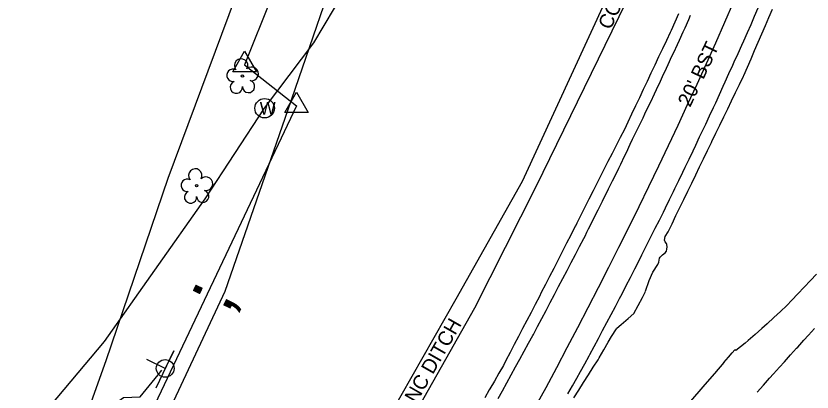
# Model space of a CAD drawing. Extents: x 1806071 to 1809844, y 912722 to 917035.
# Drawn here: x 1807362.2 to 1807582.5, y 914421.2 to 914525.2 of the extents above; entities that cross this region are included whole.
import ezdxf

# ---------------------------------------------------------------- set-up
doc = ezdxf.new("R2010")
doc.units = 0
for name, color, linetype in [('Exist Horizontal Alignment', 7, 'Continuous'), ('Exist Other Culture Fence Line', 7, 'Continuous'), ('Exist Right of Way Control of Access CA Symbol CELL', 7, 'Continuous'), ('Exist Right of Way Line', 7, 'Continuous'), ('Exist Right of Way Monument CELL', 7, 'Continuous'), ('Exist Roads Curbs', 7, 'Continuous'), ('Exist Roads EOP', 7, 'Continuous'), ('Exist Roads EOP Other', 7, 'Continuous'), ('Exist Roads EOP Text', 7, 'Continuous'), ('Exist Roads EOT', 7, 'Continuous'), ('Exist Structure Minor Paved Ditch or Gutter', 7, 'Continuous'), ('Exist Structure Minor Paved Ditch or Gutter Text', 7, 'Continuous'), ('Exist Utilities Power Joint Use Telephone CELL', 7, 'Continuous'), ('Exist Utilities Telephone UG Cable SUE LOS B', 7, 'Continuous'), ('Exist Utilities Water Manhole CELL', 7, 'Continuous'), ('Exist Utilities Water UG Line SUE LOS B', 7, 'Continuous'), ('Exist Vegetation Tree CELL', 7, 'Continuous')]:
    doc.layers.add(name, color=color, linetype=linetype)

msp = doc.modelspace()

# ---------------------------------------------------------------- linework, layer by layer
at = {"layer": 'Exist Horizontal Alignment'}
msp.add_arc((1806248.23, 915102.55), 1432.39, 321.65643, 337.65643, dxfattribs=at)
at = {"layer": 'Exist Other Culture Fence Line'}
for points in [[(1807420.06, 914449.08), (1807437.56, 914499.34), (1807454.43, 914548.48), (1807469.99, 914594.83), (1807485.68, 914641.45), (1807500.22, 914684.48), (1807514.26, 914726.68), (1807527.29, 914765.96), (1807541.47, 914807.7), (1807554.84, 914848.72), (1807568.79, 914890.48), (1807589.07, 914952.46), (1807599.72, 914988.41), (1807613.51, 915037.41), (1807624.28, 915075.41), (1807640.3, 915130.15), (1807650.98, 915169.04)], [(1806951.65, 913841.13), (1806983.44, 913875.99), (1807013.14, 913908.4), (1807047.06, 913945.66), (1807072.1, 913972.65), (1807103.97, 914007.22), (1807136.36, 914042.6), (1807170.27, 914079.29), (1807203.63, 914115.49), (1807234.9, 914151.15), (1807263.39, 914186.29), (1807290.32, 914222.94), (1807319.14, 914263.94), (1807345.33, 914304.29), (1807362.24, 914332.3), (1807387.67, 914379.81), (1807420.06, 914449.08)]]:
    msp.add_lwpolyline(points, dxfattribs=at)
at = {"layer": 'Exist Right of Way Control of Access CA Symbol CELL'}
msp.add_line((1807417.18, 914452.58), (1807417.18, 914452.58), dxfattribs=at)
at = {"layer": 'Exist Right of Way Line'}
for p, q in [((1807526.22, 914764.33), (1807425.5, 914511.68)), ((1807425.5, 914511.68), (1807439.85, 914500.36)), ((1807439.85, 914500.36), (1807384.85, 914384.43))]:
    msp.add_line(p, q, dxfattribs=at)
at = {"layer": 'Exist Right of Way Monument CELL'}
for p, q in [((1807425.5, 914511.68), (1807425.5, 914511.68)), ((1807439.85, 914500.36), (1807439.85, 914500.36))]:
    msp.add_line(p, q, dxfattribs=at)
for points in [[(1807422.25, 914509.79), (1807425.5, 914515.43), (1807428.74, 914509.79)], [(1807436.6, 914498.47), (1807439.85, 914504.11), (1807443.1, 914498.47)]]:
    msp.add_lwpolyline(points, close=True, dxfattribs=at)
at = {"layer": 'Exist Roads Curbs'}
for points in [[(1807558.07, 914429.35), (1807559.37, 914430.87), (1807560.35, 914432.01), (1807561.12, 914432.9)], [(1807558.06, 914429.35), (1807555.47, 914426.31), (1807552.85, 914423.3), (1807548.27, 914418)]]:
    msp.add_lwpolyline(points, dxfattribs=at)
at = {"layer": 'Exist Roads EOP'}
msp.add_line((1807364.11, 914365.32), (1807387.16, 914429.97), dxfattribs=at)
for points in [[(1807545.5, 914525.78), (1807544.48, 914523.49), (1807543.47, 914521.21), (1807543.23, 914520.67), (1807542.16, 914518.41), (1807541.09, 914516.14), (1807540.02, 914513.88), (1807538.96, 914511.62), (1807537.89, 914509.36), (1807536.82, 914507.1), (1807535.75, 914504.84), (1807534.69, 914502.58), (1807533.62, 914500.32), (1807532.55, 914498.06), (1807531.48, 914495.8), (1807530.55, 914493.83), (1807529.41, 914491.61), (1807528.27, 914489.38), (1807527.13, 914487.16), (1807526, 914484.93), (1807524.86, 914482.71), (1807524.13, 914481.29), (1807523.01, 914479.06), (1807521.88, 914476.82), (1807520.76, 914474.59), (1807519.64, 914472.36), (1807518.51, 914470.12), (1807517.39, 914467.89), (1807516.99, 914467.09)], [(1807536.4, 914449.07), (1807537.42, 914452.07), (1807538.47, 914454.36), (1807539.78, 914456.49), (1807540.05, 914457.08), (1807540.27, 914458.24), (1807540.48, 914458.54), (1807541.12, 914459.17), (1807541.85, 914459.66), (1807542.16, 914460.15), (1807542.3, 914460.71), (1807542.39, 914461.39), (1807542.34, 914461.98), (1807542.18, 914462.32), (1807541.82, 914462.76), (1807541.68, 914463.25), (1807541.82, 914464.18), (1807542.65, 914465.49), (1807543.74, 914467.74), (1807544.83, 914469.99), (1807545.92, 914472.24), (1807547.01, 914474.48), (1807548.1, 914476.73), (1807549.19, 914478.98), (1807550.28, 914481.23), (1807551.37, 914483.48), (1807552.46, 914485.73), (1807553.55, 914487.98), (1807554.64, 914490.23), (1807554.79, 914490.53), (1807555.88, 914492.78), (1807556.96, 914495.03), (1807558.05, 914497.28), (1807559.14, 914499.53), (1807560.23, 914501.78), (1807561.31, 914504.03), (1807562.4, 914506.28), (1807563.49, 914508.53), (1807563.6, 914508.77), (1807564.6, 914511.06), (1807565.59, 914513.36), (1807566.59, 914515.65), (1807567.59, 914517.94), (1807568.58, 914520.24), (1807569.58, 914522.53), (1807570.56, 914524.83), (1807571.55, 914527.12)], [(1807516.98, 914467.07), (1807515.72, 914464.59), (1807514.58, 914462.36), (1807513.44, 914460.14), (1807513.27, 914459.81), (1807512.13, 914457.58), (1807510.99, 914455.36), (1807509.85, 914453.13), (1807508.7, 914450.91), (1807507.56, 914448.69), (1807507.03, 914447.65), (1807505.87, 914445.44), (1807504.72, 914443.22), (1807503.56, 914441), (1807502.4, 914438.79), (1807501.25, 914436.57), (1807500.09, 914434.35), (1807498.94, 914432.14), (1807497.78, 914429.92), (1807497.07, 914428.55), (1807495.82, 914426.38), (1807494.58, 914424.22), (1807493.33, 914422.05), (1807493.19, 914421.8), (1807491.94, 914419.64)], [(1807583.75, 914453.83), (1807582.03, 914452.02), (1807580.31, 914450.2), (1807578.58, 914448.39), (1807576.86, 914446.58), (1807575.54, 914445.18), (1807573.71, 914443.49), (1807571.87, 914441.79), (1807570.04, 914440.09), (1807568.62, 914438.78), (1807566.73, 914437.14), (1807564.84, 914435.5), (1807563.97, 914434.75), (1807561.37, 914432.69), (1807561.12, 914432.9)], [(1807516.57, 914419.61), (1807517.91, 914421.71), (1807519.26, 914423.82), (1807520.6, 914425.93), (1807521.94, 914428.04), (1807523.29, 914430.15), (1807523.62, 914430.66), (1807524.84, 914432.85), (1807526.06, 914435.03), (1807526.95, 914436.61), (1807528.33, 914438.7), (1807528.42, 914438.85), (1807529.69, 914439.86), (1807531.56, 914441.52), (1807533.18, 914442.96), (1807534.35, 914445.17), (1807535.52, 914447.38), (1807536.39, 914449.03)]]:
    msp.add_lwpolyline(points, dxfattribs=at)
at = {"layer": 'Exist Roads EOP Other'}
for p, q in [((1807404.33, 914480.31), (1807453.9, 914613.77)), ((1807387.16, 914429.97), (1807404.33, 914480.31))]:
    msp.add_line(p, q, dxfattribs=at)
at = {"layer": 'Exist Roads EOT'}
for points in [[(1807532.23, 914452.9), (1807533.44, 914455.26), (1807534.25, 914456.89), (1807535.37, 914459.12), (1807536.5, 914461.35), (1807536.67, 914461.7), (1807537.8, 914463.94), (1807538.92, 914466.17), (1807539.09, 914466.51), (1807540.23, 914468.74), (1807541.36, 914470.97), (1807541.97, 914472.17), (1807543.06, 914474.42), (1807544.15, 914476.67), (1807544.54, 914477.47), (1807545.63, 914479.72), (1807546.72, 914481.98), (1807547.4, 914483.4), (1807548.48, 914485.65), (1807549.56, 914487.91), (1807550.32, 914489.49), (1807551.37, 914491.75), (1807552.43, 914494.02), (1807553.05, 914495.33), (1807554.12, 914497.59), (1807555.19, 914499.85), (1807555.83, 914501.2), (1807556.85, 914503.48), (1807557.88, 914505.76), (1807558.45, 914507.02), (1807559.49, 914509.3), (1807560.53, 914511.57), (1807560.97, 914512.53), (1807561.99, 914514.82), (1807563.01, 914517.1), (1807563.56, 914518.33), (1807564.59, 914520.61), (1807565.6, 914522.86), (1807566.59, 914525.16), (1807567.6, 914527.49)], [(1807519.67, 914464.35), (1807520.19, 914465.39), (1807520.66, 914466.34), (1807521.42, 914467.9), (1807522.14, 914469.31), (1807523.26, 914471.55), (1807523.38, 914471.78), (1807524.5, 914474.02), (1807524.82, 914474.68), (1807525.95, 914476.91), (1807526.2, 914477.41), (1807527.31, 914479.65), (1807527.9, 914480.82), (1807528.99, 914483.08), (1807529.54, 914484.23), (1807530.63, 914486.48), (1807531.11, 914487.46), (1807532.18, 914489.72), (1807532.84, 914491.1), (1807533.93, 914493.35), (1807534.64, 914494.81), (1807535.73, 914497.06), (1807536.25, 914498.15), (1807537.33, 914500.41), (1807537.83, 914501.46), (1807538.9, 914503.72), (1807539.46, 914504.91), (1807540.52, 914507.17), (1807541.12, 914508.46), (1807542.18, 914510.73), (1807542.68, 914511.78), (1807543.72, 914514.05), (1807544.2, 914515.09), (1807545.25, 914517.36), (1807545.8, 914518.55), (1807546.82, 914520.84), (1807547.33, 914521.97), (1807548.35, 914524.25), (1807548.88, 914525.43)], [(1807495.6, 914419.38), (1807496.81, 914421.57), (1807498.01, 914423.75), (1807499.22, 914425.94), (1807500.43, 914428.13), (1807501.64, 914430.32), (1807502.85, 914432.51), (1807504.06, 914434.7), (1807505.27, 914436.88), (1807505.39, 914437.11), (1807506.55, 914439.32), (1807507.71, 914441.54), (1807508.87, 914443.75), (1807510.04, 914445.97), (1807511.2, 914448.18), (1807512.36, 914450.39), (1807513.52, 914452.61), (1807514.68, 914454.82), (1807515.84, 914457.04), (1807517, 914459.25), (1807518.16, 914461.47), (1807519.32, 914463.68), (1807519.66, 914464.32)], [(1807514.91, 914420.74), (1807516.17, 914422.9), (1807517.42, 914425.07), (1807518.39, 914426.84), (1807519.59, 914429.03), (1807520.8, 914431.23), (1807521, 914431.6), (1807522.17, 914433.81), (1807523.35, 914436.01), (1807524.53, 914438.22), (1807525.71, 914440.42), (1807526.88, 914442.63), (1807528.06, 914444.84), (1807529.24, 914447.04), (1807529.94, 914448.41), (1807531.08, 914450.64), (1807532.21, 914452.87)], [(1807567.26, 914421.2), (1807569, 914423.15), (1807570.69, 914425), (1807571.8, 914426.22), (1807573.48, 914428.07), (1807574.86, 914429.6), (1807576.53, 914431.46), (1807578.21, 914433.31), (1807578.53, 914433.66), (1807580.21, 914435.51), (1807581.5, 914436.94), (1807583.18, 914438.78)]]:
    msp.add_lwpolyline(points, dxfattribs=at)
at = {"layer": 'Exist Structure Minor Paved Ditch or Gutter'}
for points in [[(1807546.15, 914577.54), (1807529.9, 914539.49), (1807502.29, 914479.4), (1807483.96, 914446.87), (1807459.55, 914404.11), (1807434.92, 914363.15), (1807436.63, 914361.7)], [(1807439.65, 914359.8), (1807464.74, 914401.26), (1807489.22, 914444.52), (1807506.17, 914478.05), (1807534.83, 914536.85), (1807551.23, 914575.61)]]:
    msp.add_lwpolyline(points, dxfattribs=at)
at = {"layer": 'Exist Utilities Power Joint Use Telephone CELL'}
msp.add_line((1807403.51, 914427.75), (1807403.51, 914427.75), dxfattribs=at)
msp.add_lwpolyline([(1807400.97, 914422.38), (1807405.86, 914432.61), (1807403.53, 914427.74), (1807398.43, 914430.16)], dxfattribs=at)
msp.add_circle((1807403.51, 914427.75), 2.45, dxfattribs=at)
at = {"layer": 'Exist Utilities Telephone UG Cable SUE LOS B'}
msp.add_lwpolyline([(1807353.58, 914404.22), (1807354.22, 914407.81), (1807382.31, 914412.76), (1807392, 914419.67), (1807396.58, 914419.84), (1807401.55, 914425.99), (1807402.58, 914427.23)], dxfattribs=at)
at = {"layer": 'Exist Utilities Water Manhole CELL'}
msp.add_line((1807431.02, 914499.69), (1807431.02, 914499.69), dxfattribs=at)
msp.add_circle((1807431.02, 914499.69), 2.69, dxfattribs=at)
at = {"layer": 'Exist Utilities Water UG Line SUE LOS B'}
for points in [[(1807431.02, 914499.69), (1807444.63, 914517.75), (1807458.92, 914541.8)], [(1806934.01, 913876.79), (1806942.74, 913886.69), (1806979.16, 913924.81), (1807020.1, 913968.31), (1807057.54, 914008.89), (1807096.91, 914053.52), (1807130.38, 914090.29), (1807169.81, 914133.74), (1807206.7, 914175.78), (1807241.81, 914220.76), (1807276.28, 914269.15), (1807304.66, 914309.76), (1807334.37, 914357.07), (1807347.65, 914376.89), (1807360.82, 914396.29), (1807368.31, 914413.26), (1807386.71, 914435.17), (1807414.54, 914474.63), (1807431.02, 914499.69)]]:
    msp.add_lwpolyline(points, dxfattribs=at)
at = {"layer": 'Exist Vegetation Tree CELL'}
for p, q in [((1807424.9, 914508.61), (1807424.9, 914508.61)), ((1807412.22, 914478.24), (1807412.22, 914478.24))]:
    msp.add_line(p, q, dxfattribs=at)
for centre in [(1807424.9, 914508.61), (1807412.22, 914478.24)]:
    msp.add_circle(centre, 0.326, dxfattribs=at)
for centre, radius, start, end in [((1807424.51, 914511.49), 1.86, 330.1651, 219.7134), ((1807422.29, 914508.77), 1.73, 62.6636, 279.3457), ((1807427.45, 914509.2), 1.9, 257.1011, 134.1999), ((1807423.2, 914505.49), 1.69, 111.5671, 6.231), ((1807426.57, 914505.71), 1.7, 181.2822, 74.56), ((1807411.84, 914481.11), 1.86, 330.1651, 219.7134), ((1807409.62, 914478.39), 1.73, 62.6636, 279.3457), ((1807414.77, 914478.83), 1.9, 257.1011, 134.1999), ((1807410.52, 914475.12), 1.69, 111.5671, 6.231), ((1807413.89, 914475.34), 1.7, 181.2822, 74.56)]:
    msp.add_arc(centre, radius, start, end, dxfattribs=at)

# ---------------------------------------------------------------- texts
at = {"layer": 'Exist Right of Way Control of Access CA Symbol CELL'}
msp.add_text(';', height=15, rotation=64.6167, dxfattribs=at).set_placement((1807420.74, 914442.59))
at = {"layer": 'Exist Roads EOP Text'}
msp.add_text("20' BST", height=4, rotation=64.6096, dxfattribs=at).set_placement((1807548.74, 914499.78))
at = {"layer": 'Exist Structure Minor Paved Ditch or Gutter Text'}
for rotation, p in [(65.3262, (1807526.71, 914521.16)), (60.276, (1807469.01, 914410.9))]:
    msp.add_text('CONC DITCH', height=4, rotation=rotation, dxfattribs=at).set_placement(p)
at = {"layer": 'Exist Utilities Water Manhole CELL'}
msp.add_text('W', height=3.5, dxfattribs=at).set_placement((1807429.67, 914497.94))

doc.saveas('drawing.dxf')
